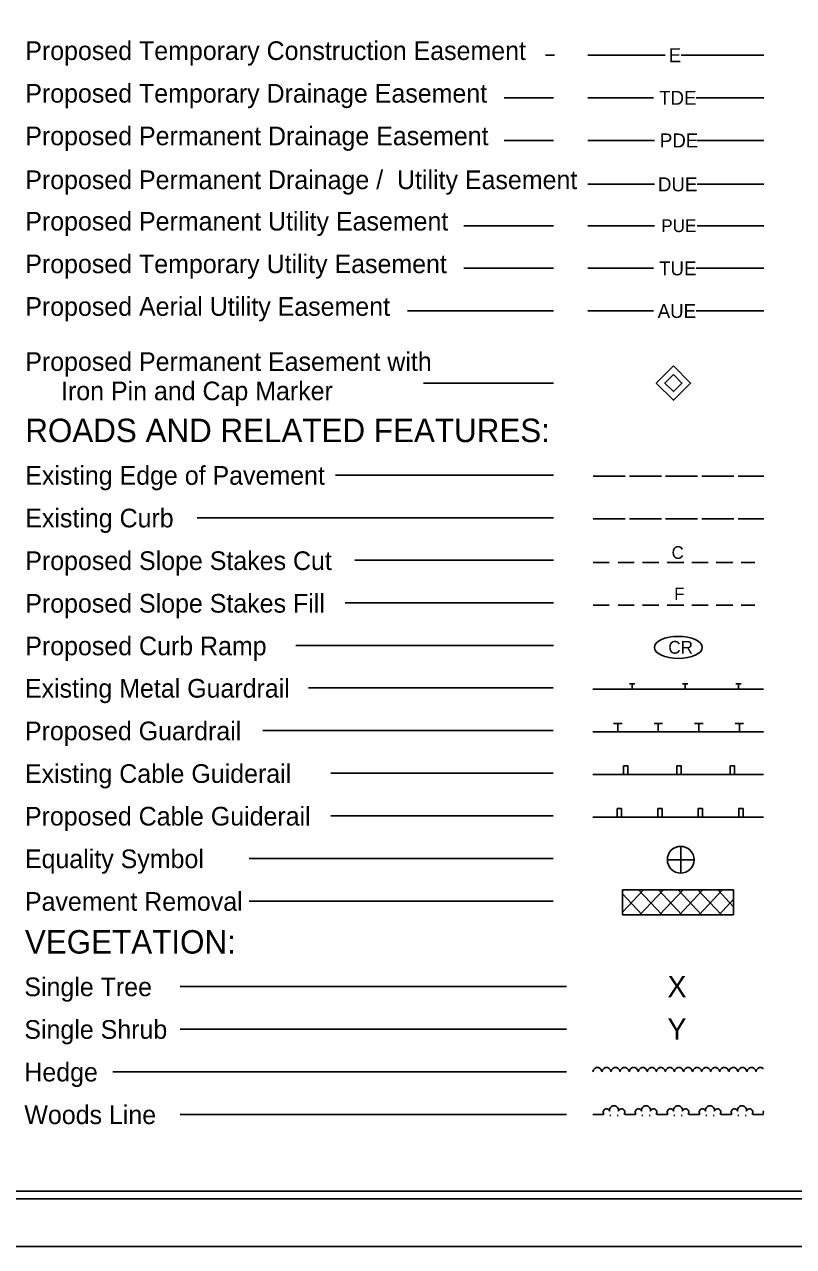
# Model space of a CAD drawing. Extents: x 10000 to 11684, y 10000 to 11100.
# Drawn here: x 10561 to 10922, y 10000 to 10573 of the extents above; entities that cross this region are included whole.
import ezdxf

# ---------------------------------------------------------------- set-up
doc = ezdxf.new("R2010")
doc.units = 0
for name, color, linetype in [('Prop Easement Permanent Drainage Utility', 7, 'Continuous'), ('Prop ROW Permanent Easement CELL', 7, 'Continuous'), ('Prop WCC CELL', 7, 'Continuous'), ('Sheet Cutting Line CELL', 7, 'Continuous'), ('Sheet Plot Border Inside CELL', 7, 'Continuous'), ('Sheet Plot Border Outside CELL', 7, 'Continuous'), ('Sheet Symbology CELL', 7, 'Continuous')]:
    doc.layers.add(name, color=color, linetype=linetype)

msp = doc.modelspace()

# ---------------------------------------------------------------- linework, layer by layer
at = {"layer": 'Prop Easement Permanent Drainage Utility'}
for p, q in [((10825.5, 10498.35), (10856.8, 10498.35)), ((10876.8, 10498.35), (10908, 10498.35))]:
    msp.add_line(p, q, dxfattribs=at)
at = {"layer": 'Prop ROW Permanent Easement CELL'}
msp.add_line((10865.64, 10405.11), (10865.64, 10405.11), dxfattribs=at)
for points in [[(10865.64, 10413.16), (10873.7, 10405.1), (10865.64, 10397.05), (10857.59, 10405.1)], [(10865.64, 10409.13), (10869.67, 10405.1), (10865.64, 10401.08), (10861.62, 10405.1)]]:
    msp.add_lwpolyline(points, close=True, dxfattribs=at)
at = {"layer": 'Prop WCC CELL'}
msp.add_ellipse((10867.96, 10281.08), major_axis=(11.21, 0), ratio=0.462467, dxfattribs=at)
at = {"layer": 'Sheet Cutting Line CELL'}
msp.add_line((10000, 10000), (11684, 10000), dxfattribs=at)
at = {"layer": 'Sheet Plot Border Inside CELL'}
msp.add_lwpolyline([(10013, 10022.45), (11679.5, 10022.45), (11679.5, 11077.55), (10013, 11077.55)], close=True, dxfattribs=at)
at = {"layer": 'Sheet Plot Border Outside CELL'}
msp.add_lwpolyline([(10000, 10000), (11684, 10000), (11684, 11100), (10000, 11100)], close=True, dxfattribs=at)
at = {"layer": 'Sheet Symbology CELL'}
for p, q in [((10809.85, 10558.94), (10805.68, 10558.94)), ((10825.5, 10558.94), (10828.11, 10558.94)), ((10828.11, 10558.94), (10861.86, 10558.94)), ((10869.36, 10558.94), (10903.11, 10558.94)), ((10903.11, 10558.94), (10908, 10558.94)), ((10809.47, 10538.94), (10786.32, 10538.94)), ((10825.5, 10538.94), (10828.85, 10538.94)), ((10828.85, 10538.94), (10856.35, 10538.94)), ((10876.35, 10538.94), (10903.85, 10538.94)), ((10903.85, 10538.94), (10908, 10538.94)), ((10809.47, 10518.94), (10786.32, 10518.94)), ((10825.5, 10518.94), (10829.3, 10518.94)), ((10829.3, 10518.94), (10856.8, 10518.94)), ((10876.8, 10518.94), (10904.3, 10518.94)), ((10904.3, 10518.94), (10908, 10518.94)), ((10809.47, 10478.93), (10767.33, 10478.93)), ((10825.5, 10478.93), (10829.34, 10478.93)), ((10829.34, 10478.93), (10856.84, 10478.93)), ((10876.84, 10478.93), (10904.34, 10478.93)), ((10904.34, 10478.93), (10908, 10478.93)), ((10809.47, 10458.93), (10767.33, 10458.93)), ((10825.5, 10458.93), (10828.85, 10458.93)), ((10828.85, 10458.93), (10856.35, 10458.93)), ((10876.35, 10458.93), (10903.85, 10458.93)), ((10903.85, 10458.93), (10908, 10458.93)), ((10809.47, 10438.93), (10741.01, 10438.93)), ((10825.5, 10438.93), (10828.85, 10438.93)), ((10828.85, 10438.93), (10856.35, 10438.93)), ((10876.35, 10438.93), (10903.85, 10438.93)), ((10903.85, 10438.93), (10908, 10438.93)), ((10809.47, 10405.1), (10748.46, 10405.1)), ((10809.47, 10361.95), (10707.12, 10361.95)), ((10828, 10361.37), (10843, 10361.37)), ((10845, 10361.37), (10860, 10361.37)), ((10862, 10361.37), (10877, 10361.37)), ((10879, 10361.37), (10894, 10361.37)), ((10896, 10361.37), (10908, 10361.37)), ((10809.47, 10341.95), (10642.32, 10341.95)), ((10828, 10341.37), (10843, 10341.37)), ((10845, 10341.37), (10860, 10341.37)), ((10862, 10341.37), (10877, 10341.37)), ((10879, 10341.37), (10894, 10341.37)), ((10896, 10341.37), (10908, 10341.37)), ((10809.47, 10321.95), (10716.28, 10321.95)), ((10828, 10320.9), (10835.6, 10320.9)), ((10847.3, 10320.9), (10839.75, 10320.9)), ((10858.8, 10320.9), (10851.2, 10320.9)), ((10870.55, 10320.9), (10862.75, 10320.9)), ((10882, 10320.9), (10874.25, 10320.9)), ((10893.55, 10320.9), (10885.7, 10320.9)), ((10903.85, 10320.9), (10897.45, 10320.9)), ((10809.47, 10301.95), (10711.73, 10301.95)), ((10828, 10300.9), (10835.6, 10300.9)), ((10847.3, 10300.9), (10839.75, 10300.9)), ((10858.8, 10300.9), (10851.2, 10300.9)), ((10870.55, 10300.9), (10862.75, 10300.9)), ((10882, 10300.9), (10874.25, 10300.9)), ((10893.55, 10300.9), (10885.7, 10300.9)), ((10903.85, 10300.9), (10897.45, 10300.9)), ((10809.47, 10281.95), (10688.54, 10281.95)), ((10844.98, 10263.99), (10847.48, 10263.99)), ((10846.23, 10261.49), (10846.23, 10263.99)), ((10869.98, 10263.99), (10872.48, 10263.99)), ((10871.23, 10261.49), (10871.23, 10263.99)), ((10894.98, 10263.99), (10897.48, 10263.99)), ((10896.23, 10261.49), (10896.23, 10263.99)), ((10809.31, 10262.07), (10694.47, 10262.07)), ((10827.84, 10261.49), (10907.84, 10261.49)), ((10809.31, 10242.07), (10673.07, 10242.07)), ((10907.84, 10241.49), (10827.84, 10241.49)), ((10837.57, 10245.44), (10841.57, 10245.44)), ((10839.57, 10241.49), (10839.57, 10245.44)), ((10856.57, 10245.44), (10860.57, 10245.44)), ((10858.57, 10241.49), (10858.57, 10245.44)), ((10875.57, 10245.44), (10879.57, 10245.44)), ((10877.57, 10241.49), (10877.57, 10245.44)), ((10894.57, 10245.44), (10898.57, 10245.44)), ((10896.57, 10241.49), (10896.57, 10245.44)), ((10809.31, 10222.07), (10705.01, 10222.07)), ((10827.84, 10221.49), (10907.84, 10221.49)), ((10809.31, 10202.07), (10705.01, 10202.07)), ((10827.84, 10201.49), (10907.84, 10201.49)), ((10869.07, 10187.73), (10869.07, 10181.48)), ((10809.31, 10182.07), (10666.69, 10182.07)), ((10862.82, 10181.48), (10869.07, 10181.48)), ((10869.07, 10181.48), (10869.07, 10175.23)), ((10869.07, 10181.48), (10875.32, 10181.48)), ((10841.79, 10167.35), (10893.89, 10167.35)), ((10841.79, 10155.65), (10841.79, 10167.35)), ((10841.79, 10166.75), (10842.34, 10167.35)), ((10841.79, 10156.8), (10851.64, 10167.35)), ((10851.04, 10155.65), (10841.79, 10165.55)), ((10860.34, 10155.65), (10849.34, 10167.35)), ((10849.94, 10155.65), (10860.94, 10167.35)), ((10869.59, 10155.65), (10858.64, 10167.35)), ((10859.19, 10155.65), (10870.24, 10167.35)), ((10878.89, 10155.65), (10867.89, 10167.35)), ((10868.49, 10155.65), (10879.49, 10167.35)), ((10888.19, 10155.65), (10877.14, 10167.35)), ((10877.79, 10155.65), (10888.74, 10167.35)), ((10893.89, 10159.4), (10886.44, 10167.35)), ((10893.89, 10167.35), (10893.89, 10155.65)), ((10809.31, 10162.07), (10666.69, 10162.07)), ((10887.04, 10155.65), (10893.89, 10162.95)), ((10893.89, 10155.65), (10841.79, 10155.65)), ((10815.45, 10122), (10634.32, 10122)), ((10815.45, 10102), (10634.32, 10102)), ((10815.45, 10082), (10602.76, 10082)), ((10827.84, 10082), (10828.14, 10082.95)), ((10828.14, 10082.95), (10828.74, 10083.6)), ((10828.74, 10083.6), (10829.54, 10084.05)), ((10829.54, 10084.05), (10830.49, 10084.05)), ((10830.49, 10084.05), (10831.29, 10083.55)), ((10831.29, 10083.55), (10831.84, 10082.9)), ((10831.84, 10082.9), (10832.04, 10082.05)), ((10832.09, 10082), (10832.39, 10082.95)), ((10832.39, 10082.95), (10832.99, 10083.6)), ((10832.99, 10083.6), (10833.79, 10084.05)), ((10833.79, 10084.05), (10834.74, 10084.05)), ((10834.74, 10084.05), (10835.54, 10083.55)), ((10835.54, 10083.55), (10836.09, 10082.9)), ((10836.09, 10082.9), (10836.29, 10082.05)), ((10836.34, 10082), (10836.64, 10082.95)), ((10836.64, 10082.95), (10837.24, 10083.6)), ((10837.24, 10083.6), (10838.04, 10084.05)), ((10838.04, 10084.05), (10838.99, 10084.05)), ((10838.99, 10084.05), (10839.79, 10083.55)), ((10839.79, 10083.55), (10840.34, 10082.9)), ((10840.34, 10082.9), (10840.54, 10082.05)), ((10840.59, 10082), (10840.89, 10082.95)), ((10840.89, 10082.95), (10841.49, 10083.6)), ((10841.49, 10083.6), (10842.29, 10084.05)), ((10842.29, 10084.05), (10843.24, 10084.05)), ((10843.24, 10084.05), (10844.04, 10083.55)), ((10844.04, 10083.55), (10844.59, 10082.9)), ((10844.59, 10082.9), (10844.79, 10082.05)), ((10844.84, 10082), (10845.14, 10082.95)), ((10845.14, 10082.95), (10845.74, 10083.6)), ((10845.74, 10083.6), (10846.54, 10084.05)), ((10846.54, 10084.05), (10847.49, 10084.05)), ((10847.49, 10084.05), (10848.29, 10083.55)), ((10848.29, 10083.55), (10848.84, 10082.9)), ((10848.84, 10082.9), (10849.04, 10082.05)), ((10849.09, 10082), (10849.39, 10082.95)), ((10849.39, 10082.95), (10849.99, 10083.6)), ((10849.99, 10083.6), (10850.79, 10084.05)), ((10850.79, 10084.05), (10851.74, 10084.05)), ((10851.74, 10084.05), (10852.54, 10083.55)), ((10852.54, 10083.55), (10853.09, 10082.9)), ((10853.09, 10082.9), (10853.29, 10082.05)), ((10853.34, 10082), (10853.64, 10082.95)), ((10853.64, 10082.95), (10854.24, 10083.6)), ((10854.24, 10083.6), (10855.04, 10084.05)), ((10855.04, 10084.05), (10855.99, 10084.05)), ((10855.99, 10084.05), (10856.79, 10083.55)), ((10856.79, 10083.55), (10857.34, 10082.9)), ((10857.34, 10082.9), (10857.54, 10082.05)), ((10857.59, 10082), (10857.89, 10082.95)), ((10857.89, 10082.95), (10858.49, 10083.6)), ((10858.49, 10083.6), (10859.29, 10084.05)), ((10859.29, 10084.05), (10860.24, 10084.05)), ((10860.24, 10084.05), (10861.04, 10083.55)), ((10861.04, 10083.55), (10861.59, 10082.9)), ((10861.59, 10082.9), (10861.79, 10082.05)), ((10861.84, 10082), (10862.14, 10082.95)), ((10862.14, 10082.95), (10862.74, 10083.6)), ((10862.74, 10083.6), (10863.54, 10084.05)), ((10863.54, 10084.05), (10864.49, 10084.05)), ((10864.49, 10084.05), (10865.29, 10083.55)), ((10865.29, 10083.55), (10865.84, 10082.9)), ((10865.84, 10082.9), (10866.04, 10082.05)), ((10866.09, 10082), (10866.39, 10082.95)), ((10866.39, 10082.95), (10866.99, 10083.6)), ((10866.99, 10083.6), (10867.79, 10084.05)), ((10867.79, 10084.05), (10868.74, 10084.05)), ((10868.74, 10084.05), (10869.54, 10083.55)), ((10869.54, 10083.55), (10870.09, 10082.9)), ((10870.09, 10082.9), (10870.29, 10082.05)), ((10870.34, 10082), (10870.64, 10082.95)), ((10870.64, 10082.95), (10871.24, 10083.6)), ((10871.24, 10083.6), (10872.04, 10084.05)), ((10872.04, 10084.05), (10872.99, 10084.05)), ((10872.99, 10084.05), (10873.79, 10083.55)), ((10873.79, 10083.55), (10874.34, 10082.9)), ((10874.34, 10082.9), (10874.54, 10082.05)), ((10874.59, 10082), (10874.89, 10082.95)), ((10874.89, 10082.95), (10875.49, 10083.6)), ((10875.49, 10083.6), (10876.29, 10084.05)), ((10876.29, 10084.05), (10877.24, 10084.05)), ((10877.24, 10084.05), (10878.04, 10083.55)), ((10878.04, 10083.55), (10878.59, 10082.9)), ((10878.59, 10082.9), (10878.79, 10082.05)), ((10878.84, 10082), (10879.14, 10082.95)), ((10879.14, 10082.95), (10879.74, 10083.6)), ((10879.74, 10083.6), (10880.54, 10084.05)), ((10880.54, 10084.05), (10881.49, 10084.05)), ((10881.49, 10084.05), (10882.29, 10083.55)), ((10882.29, 10083.55), (10882.84, 10082.9)), ((10882.84, 10082.9), (10883.04, 10082.05)), ((10883.09, 10082), (10883.39, 10082.95)), ((10883.39, 10082.95), (10883.99, 10083.6)), ((10883.99, 10083.6), (10884.79, 10084.05)), ((10884.79, 10084.05), (10885.74, 10084.05)), ((10885.74, 10084.05), (10886.54, 10083.55)), ((10886.54, 10083.55), (10887.09, 10082.9)), ((10887.09, 10082.9), (10887.29, 10082.05)), ((10887.34, 10082), (10887.64, 10082.95)), ((10887.64, 10082.95), (10888.24, 10083.6)), ((10888.24, 10083.6), (10889.04, 10084.05)), ((10889.04, 10084.05), (10889.99, 10084.05)), ((10889.99, 10084.05), (10890.79, 10083.55)), ((10890.79, 10083.55), (10891.34, 10082.9)), ((10891.34, 10082.9), (10891.54, 10082.05)), ((10891.59, 10082), (10891.89, 10082.95)), ((10891.89, 10082.95), (10892.49, 10083.6)), ((10892.49, 10083.6), (10893.29, 10084.05)), ((10893.29, 10084.05), (10894.24, 10084.05)), ((10894.24, 10084.05), (10895.04, 10083.55)), ((10895.04, 10083.55), (10895.59, 10082.9)), ((10895.59, 10082.9), (10895.79, 10082.05)), ((10895.84, 10082), (10896.14, 10082.95)), ((10896.14, 10082.95), (10896.74, 10083.6)), ((10896.74, 10083.6), (10897.54, 10084.05)), ((10897.54, 10084.05), (10898.49, 10084.05)), ((10898.49, 10084.05), (10899.29, 10083.55)), ((10899.29, 10083.55), (10899.84, 10082.9)), ((10899.84, 10082.9), (10900.04, 10082.05)), ((10900.09, 10082), (10900.39, 10082.95)), ((10900.39, 10082.95), (10900.99, 10083.6)), ((10900.99, 10083.6), (10901.79, 10084.05)), ((10901.79, 10084.05), (10902.74, 10084.05)), ((10902.74, 10084.05), (10903.54, 10083.55)), ((10903.54, 10083.55), (10904.09, 10082.9)), ((10904.09, 10082.9), (10904.29, 10082.05)), ((10904.34, 10082), (10904.64, 10082.95)), ((10904.64, 10082.95), (10905.24, 10083.6)), ((10905.24, 10083.6), (10906.04, 10084.05)), ((10906.04, 10084.05), (10906.99, 10084.05)), ((10906.99, 10084.05), (10907.79, 10083.55)), ((10907.79, 10083.55), (10907.84, 10083.5)), ((10815.45, 10062), (10634.32, 10062)), ((10827.84, 10062), (10832.84, 10062)), ((10835.79, 10061.5), (10836.29, 10061.5)), ((10839.29, 10061.5), (10839.79, 10061.5)), ((10842.84, 10062), (10847.84, 10062)), ((10850.79, 10061.5), (10851.29, 10061.5)), ((10854.29, 10061.5), (10854.79, 10061.5)), ((10857.84, 10062), (10862.84, 10062)), ((10865.79, 10061.5), (10866.29, 10061.5)), ((10869.29, 10061.5), (10869.79, 10061.5)), ((10872.84, 10062), (10877.84, 10062)), ((10880.79, 10061.5), (10881.29, 10061.5)), ((10884.29, 10061.5), (10884.79, 10061.5)), ((10887.84, 10062), (10892.84, 10062)), ((10895.79, 10061.5), (10896.29, 10061.5)), ((10899.29, 10061.5), (10899.79, 10061.5)), ((10902.84, 10062), (10907.84, 10062))]:
    msp.add_line(p, q, dxfattribs=at)
for points in [[(11667, 11075), (10167, 11075), (10167, 10026.02), (11667, 10026.02)], [(10842.32, 10221.49), (10844.32, 10221.49), (10844.32, 10225.49), (10842.32, 10225.49)], [(10867.32, 10221.49), (10869.32, 10221.49), (10869.32, 10225.49), (10867.32, 10225.49)], [(10892.32, 10221.49), (10894.32, 10221.49), (10894.32, 10225.49), (10892.32, 10225.49)], [(10839.3, 10205.49), (10841.3, 10205.49), (10841.3, 10201.49), (10839.3, 10201.49)], [(10858.3, 10205.49), (10860.3, 10205.49), (10860.3, 10201.49), (10858.3, 10201.49)], [(10877.3, 10205.49), (10879.3, 10205.49), (10879.3, 10201.49), (10877.3, 10201.49)], [(10896.3, 10205.49), (10898.3, 10205.49), (10898.3, 10201.49), (10896.3, 10201.49)]]:
    msp.add_lwpolyline(points, close=True, dxfattribs=at)
for centre, radius, start, end in [((10869.07, 10181.48), 6.25, 89.99439, 179.99893), ((10869.07, 10181.48), 6.25, 359.99439, 89.99893), ((10869.07, 10181.48), 6.25, 179.99439, 269.99892), ((10869.07, 10181.48), 6.25, 269.99439, 359.99893), ((10834.29, 10063.01), 1.58, 18.43495, 219.23152), ((10837.79, 10064.01), 2.06, 345.96376, 194.03624), ((10841.29, 10063.01), 1.58, 320.76848, 161.56505), ((10849.29, 10063.01), 1.58, 18.43495, 219.23152), ((10852.79, 10064.01), 2.06, 345.96376, 194.03624), ((10856.29, 10063.01), 1.58, 320.76848, 161.56505), ((10864.29, 10063.01), 1.58, 18.43495, 219.23152), ((10867.79, 10064.01), 2.06, 345.96376, 194.03624), ((10871.29, 10063.01), 1.58, 320.76848, 161.56505), ((10879.29, 10063.01), 1.58, 18.43495, 219.23152), ((10882.79, 10064.01), 2.06, 345.96376, 194.03624), ((10886.29, 10063.01), 1.58, 320.76848, 161.56505), ((10894.29, 10063.01), 1.58, 18.43495, 219.23152), ((10897.79, 10064.01), 2.06, 345.96376, 194.03624), ((10901.29, 10063.01), 1.58, 320.76848, 161.56505), ((10909.29, 10063.01), 1.58, 156.25102, 203.74899)]:
    msp.add_arc(centre, radius, start, end, dxfattribs=at)

# ---------------------------------------------------------------- texts
at = {"layer": 'Prop Easement Permanent Drainage Utility'}
msp.add_text('DUE', height=6.55, dxfattribs=at).set_placement((10858.39, 10495.05))
at = {"layer": 'Prop WCC CELL'}
msp.add_text('CR', height=6, dxfattribs=at).set_placement((10863.25, 10278.13))
at = {"layer": 'Sheet Symbology CELL'}
for s, height, p in [('Proposed Temporary Construction Easement', 8.75, (10561.72, 10556.67)), ('E', 6.55, (10863.46, 10555.64)), ('Proposed Temporary Drainage Easement', 8.75, (10561.72, 10536.67)), ('TDE', 6.55, (10858.95, 10535.64)), ('Proposed Permanent Drainage Easement', 8.75, (10561.72, 10516.67)), ('PDE', 6.55, (10859.3, 10515.64)), ('Proposed Permanent Drainage /  Utility Easement', 8.75, (10561.72, 10496.09)), ('Proposed Permanent Utility Easement', 8.75, (10561.72, 10476.66)), ('PUE', 6, (10859.94, 10475.93)), ('Proposed Temporary Utility Easement', 8.75, (10561.72, 10456.66)), ('TUE', 6.55, (10858.93, 10455.63)), ('Proposed Aerial Utility Easement', 8.75, (10561.72, 10436.66)), ('AUE', 6.55, (10858.27, 10435.63)), ('Proposed Permanent Easement with', 8.75, (10561.72, 10410.8)), ('Iron Pin and Cap Marker', 8.75, (10578.48, 10397.05)), ('ROADS AND RELATED FEATURES:', 11, (10561.72, 10377.4)), ('Existing Edge of Pavement', 8.75, (10561.72, 10357.4)), ('Existing Curb', 8.75, (10561.72, 10337.4)), ('Proposed Slope Stakes Cut', 8.75, (10561.72, 10317.4)), ('C', 5.93, (10864.8, 10322.63)), ('F', 5.93, (10866, 10303.26)), ('Proposed Slope Stakes Fill', 8.75, (10561.72, 10297.4)), ('Proposed Curb Ramp', 8.75, (10561.72, 10277.4)), ('Existing Metal Guardrail', 8.75, (10561.56, 10257.52)), ('Proposed Guardrail', 8.75, (10561.57, 10237.53)), ('Existing Cable Guiderail', 8.75, (10561.57, 10217.53)), ('Proposed Cable Guiderail', 8.75, (10561.57, 10197.53)), ('Equality Symbol', 8.75, (10561.57, 10177.53)), ('Pavement Removal', 8.75, (10561.57, 10157.53)), ('VEGETATION:', 11, (10561.56, 10137.45)), ('Single Tree', 8.75, (10561.29, 10117.47)), ('X', 10, (10862.84, 10117)), ('Single Shrub', 8.75, (10561.29, 10097.47)), ('Y', 10, (10862.84, 10097)), ('Hedge', 8.75, (10561.29, 10077.47)), ('Woods Line', 8.75, (10561.29, 10057.47))]:
    msp.add_text(s, height=height, dxfattribs=at).set_placement(p)

doc.saveas('drawing.dxf')
